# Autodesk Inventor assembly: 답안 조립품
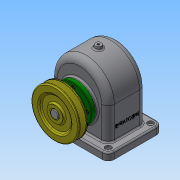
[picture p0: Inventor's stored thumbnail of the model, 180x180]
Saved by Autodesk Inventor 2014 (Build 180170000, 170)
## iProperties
Created: 2016-10
Part Number: 답안 조립품
Document SubType Name: Assembly
Designer: NET
Author: NET
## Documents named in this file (13)
- C:\Users\NET\Desktop\461007V1016\답안 조립품.iam
- C:\Users\NET\Desktop\461007V1016\답안 본체.ipt
- C:\Users\NET\Desktop\461007V1016\앞커버.ipt
- C:\Users\NET\Desktop\461007V1016\뒤커버.ipt
- C:\Users\NET\Desktop\461007V1016\볼트 M3 x 8.ipt
- C:\Users\NET\Desktop\461007V1016\볼트 M3 x 10.ipt
- C:\Users\NET\Desktop\461007V1016\오일씰 28 40 8.ipt
- C:\Users\NET\Desktop\461007V1016\축.ipt
- C:\Users\NET\Desktop\461007V1016\키 - 6 x 6 x 22.ipt
- C:\Users\NET\Desktop\461007V1016\키 - 5 x 5 x 18.ipt
- C:\Users\NET\Desktop\461007V1016\베어링 6203.ipt
- C:\Users\NET\Desktop\461007V1016\스퍼기어.ipt
- C:\Users\NET\Desktop\461007V1016\V-벨트풀리.ipt
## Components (9 placed, 3 different names)
1. V-벨트풀리:1 — 각도:2
2. ISO 4762 M3 x 10:1
3. ISO 4762 M3 x 10:2
4. ISO 4762 M3 x 10:3
5. ISO 4762 M3 x 10:4
6. ISO 4762 M3 x 8:1
7. ISO 4762 M3 x 8:2
8. ISO 4762 M3 x 8:3
9. ISO 4762 M3 x 8:4
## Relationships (1: Angle 1)
- 각도:2 [Angle]: V-벨트풀리:1
